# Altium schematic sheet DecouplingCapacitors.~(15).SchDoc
size A4
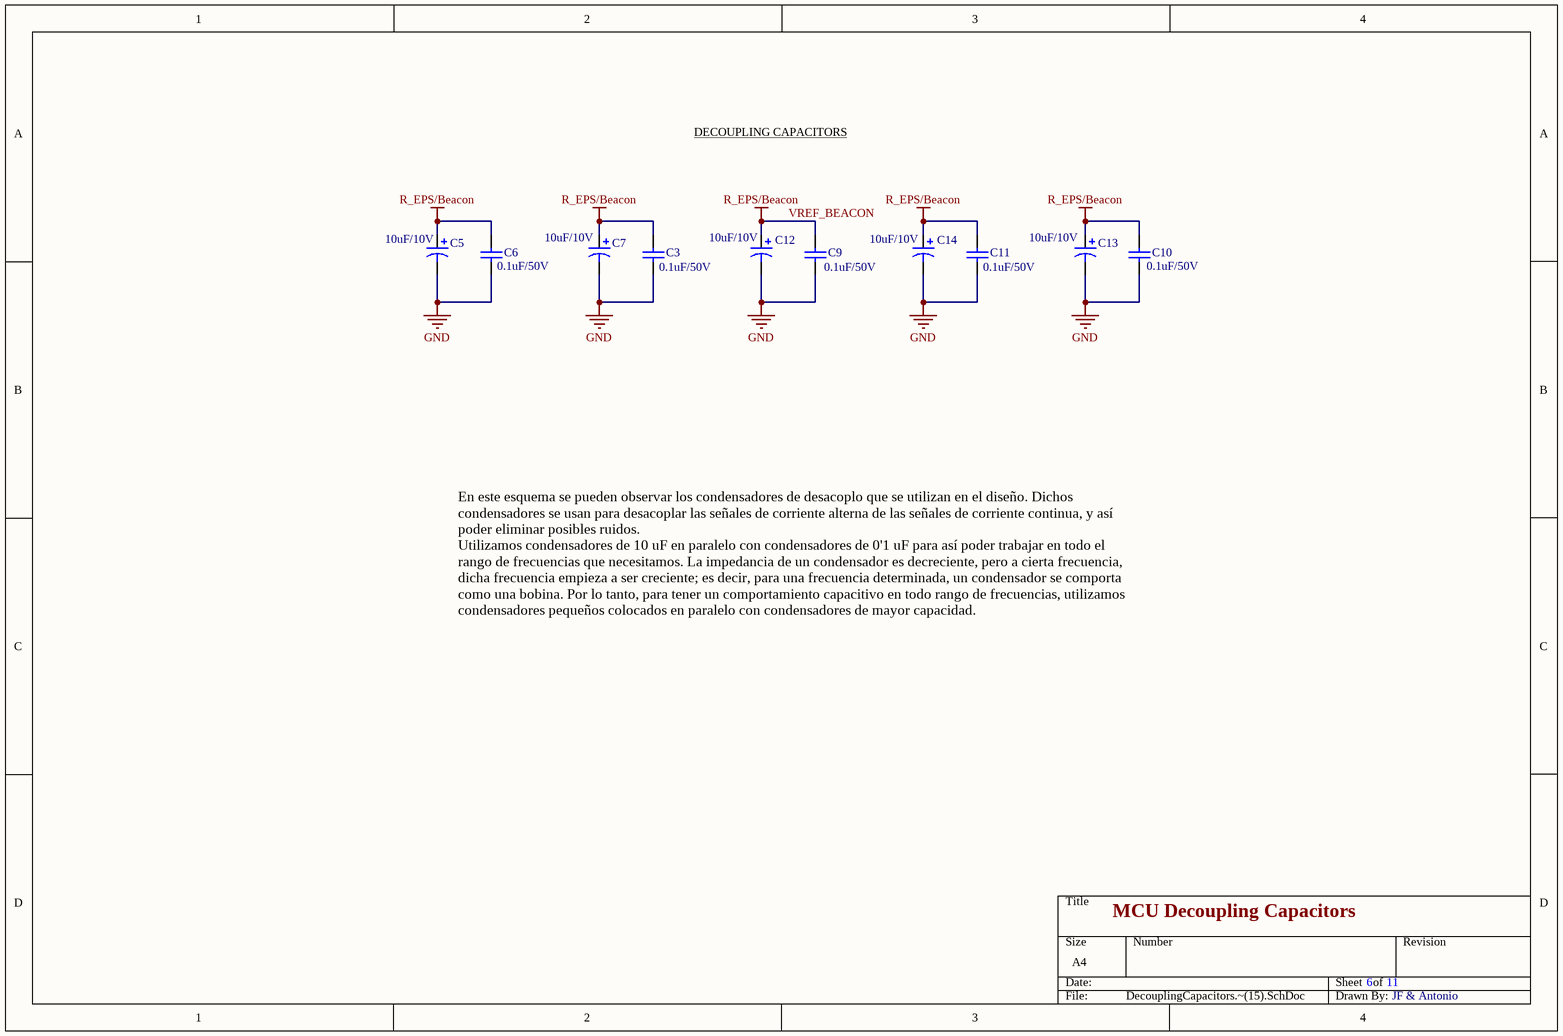
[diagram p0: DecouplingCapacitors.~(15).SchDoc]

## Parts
C3  value 0.1uF/50V  [CN]
C5  value 10uF/10V  [C10u]
C6  value 0.1uF/50V  [CN]
C7  value 10uF/10V  [C10u]
C9  value 0.1uF/50V  [CN]
C10  value 0.1uF/50V  [CN]
C11  value 0.1uF/50V  [CN]
C12  value 10uF/10V  [C10u]
C13  value 10uF/10V  [C10u]
C14  value 10uF/10V  [C10u]

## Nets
GND: C3.2 C5.2 C6.2 C7.2 C9.2 C10.2 C11.2 C12.2 C13.2 C14.2
VREF_BEACON: C3.1 C5.1 C6.1 C7.1 C9.1 C10.1 C11.1 C12.1 C13.1 C14.1  [also labelled R_EPS/Beacon]

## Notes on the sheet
- DECOUPLING CAPACITORS
- En este esquema se pueden observar los condensadores de desacoplo que se utilizan en el diseño. Dichos condensadores se usan para desacoplar las señales de corriente alterna de las señales de corriente continua, y así poder eliminar posibles ruidos.
  Utilizamos condensadores de 10 uF en paralelo con condensadores de 0'1 uF para así poder trabajar en todo el rango de frecuencias que necesitamos. La impedancia de un condensador es decreciente, pero a cierta frecuencia, dicha frecuencia empieza a ser creciente; es decir, para una frecuencia determinada, un condensador se comporta como una bobina. Por lo tanto, para tener un comportamiento capacitivo en todo rango de frecuencias, utilizamos condensadores pequeños colocados en paralelo con condensadores de mayor capacidad.
- MCU Decoupling Capacitors
- 6
- 11
- JF & Antonio

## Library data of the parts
C3 C6 C9-C11 = Cap Semi: Capacitor (Semiconductor SIM Model)
C5 C7 C12-C14 = Cap Pol3: Polarized Capacitor (Surface Mount)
